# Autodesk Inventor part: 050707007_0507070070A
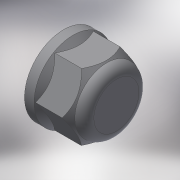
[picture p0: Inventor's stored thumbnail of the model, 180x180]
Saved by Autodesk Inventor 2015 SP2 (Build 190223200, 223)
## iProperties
Created: 2017-05
Part Number: 050707007_0507070070A
Material: Generic
Description: PLASSON CAP 3/4"
Document SubType Name: Modeling
Designer: KIM
Density: 1 g/cm^3
Appearance: Default
Author: KIM
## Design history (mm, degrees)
derived "050707.ipt"
feature "Solid1::050707.ipt"
tag "TaggingFeature1"
body "Solid1"
other parameters: "d0" = 26, "d1" = 1.6, "d2" = 24.117, "d3" = 16, "d4" = 1.6, "d5" = 135 deg, "d6" = 26.5287, "d7" = 42, "d8" = 35.7, "d9" = 34.44, "d10" = 135 deg, "d11" = 4.8, "d13" = 4.8, "d16" = 0, "Rp_" = 24.117, "E_" = 42, "H_" = 26, "l_2" = 16
